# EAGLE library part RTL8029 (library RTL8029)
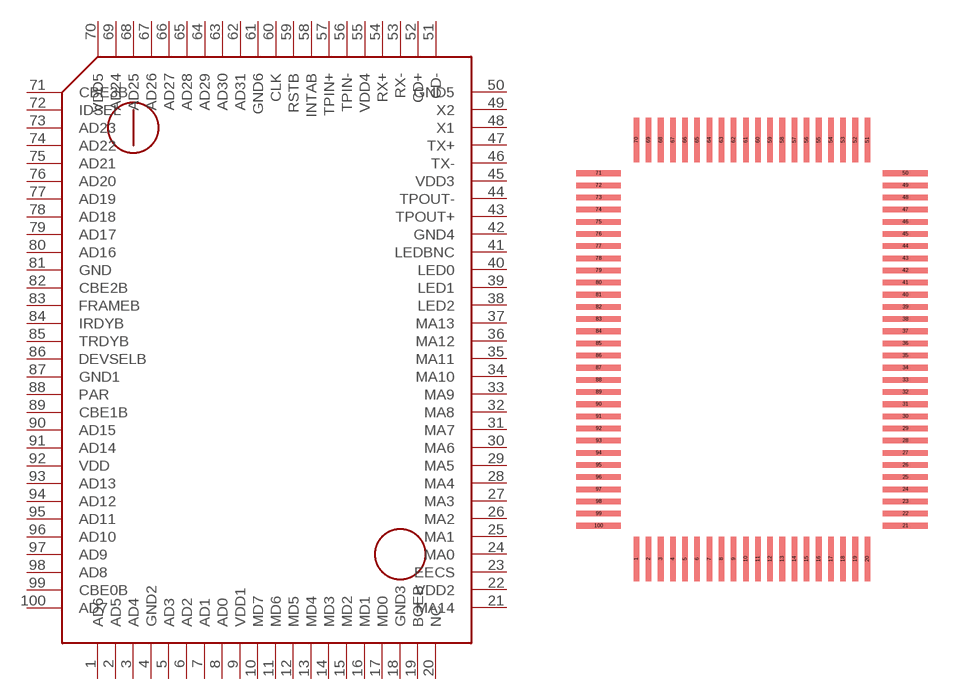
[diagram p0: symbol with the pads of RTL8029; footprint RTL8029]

Designator prefix -

## RTL8029  [RTL8029]
1  AD6
2  AD5
3  AD4
4  GND2
5  AD3
6  AD2
7  AD1
8  AD0
9  VDD1
10  MD7
11  MD6
12  MD5
13  MD4
14  MD3
15  MD2
16  MD1
17  MD0
18  GND3
19  BOEB
20  NC
21  MA14
22  VDD2
23  EECS
24  MA0
25  MA1
26  MA2
27  MA3
28  MA4
29  MA5
30  MA6
31  MA7
32  MA8
33  MA9
34  MA10
35  MA11
36  MA12
37  MA13
38  LED2
39  LED1
40  LED0
41  LEDBNC
42  GND4
43  TPOUT+
44  TPOUT-
45  VDD3
46  TX-
47  TX+
48  X1
49  X2
50  GND5
51  CD-
52  CD+
53  RX-
54  RX+
55  VDD4
56  TPIN-
57  TPIN+
58  INTAB
59  RSTB
60  CLK
61  GND6
62  AD31
63  AD30
64  AD29
65  AD28
66  AD27
67  AD26
68  AD25
69  AD24
70  VDD5
71  CBE3B
72  IDSEL
73  AD23
74  AD22
75  AD21
76  AD20
77  AD19
78  AD18
79  AD17
80  AD16
81  GND
82  CBE2B
83  FRAMEB
84  IRDYB
85  TRDYB
86  DEVSELB
87  GND1
88  PAR
89  CBE1B
90  AD15
91  AD14
92  VDD
93  AD13
94  AD12
95  AD11
96  AD10
97  AD9
98  AD8
99  CBE0B
100  AD7

## Footprint RTL8029 (pad centres in mm)
smd 0.3 x 2.4: 1 -6.175,-11.2; 2 -5.525,-11.2; 3 -4.875,-11.2; 4 -4.225,-11.2; 5 -3.575,-11.2; 6 -2.925,-11.2; 7 -2.275,-11.2; 8 -1.625,-11.2; 9 -0.975,-11.2; 10 -0.325,-11.2; 11 0.325,-11.2; 12 0.975,-11.2; 13 1.625,-11.2; 14 2.275,-11.2; 15 2.925,-11.2; 16 3.575,-11.2; 17 4.225,-11.2; 18 4.875,-11.2; 19 5.525,-11.2; 20 6.175,-11.2; 51 6.175,11.2; 52 5.525,11.2; 53 4.875,11.2; 54 4.225,11.2; 55 3.575,11.2; 56 2.925,11.2; 57 2.275,11.2; 58 1.625,11.2; 59 0.975,11.2; 60 0.325,11.2; 61 -0.325,11.2; 62 -0.975,11.2; 63 -1.625,11.2; 64 -2.275,11.2; 65 -2.925,11.2; 66 -3.575,11.2; 67 -4.225,11.2; 68 -4.875,11.2; 69 -5.525,11.2; 70 -6.175,11.2
smd 2.4 x 0.3: 21 8.2,-9.425; 22 8.2,-8.775; 23 8.2,-8.125; 24 8.2,-7.475; 25 8.2,-6.825; 26 8.2,-6.175; 27 8.2,-5.525; 28 8.2,-4.875; 29 8.2,-4.225; 30 8.2,-3.575; 31 8.2,-2.925; 32 8.2,-2.275; 33 8.2,-1.625; 34 8.2,-0.975; 35 8.2,-0.325; 36 8.2,0.325; 37 8.2,0.975; 38 8.2,1.625; 39 8.2,2.275; 40 8.2,2.925; 41 8.2,3.575; 42 8.2,4.225; 43 8.2,4.875; 44 8.2,5.525; 45 8.2,6.175; 46 8.2,6.825; 47 8.2,7.475; 48 8.2,8.125; 49 8.2,8.775; 50 8.2,9.425; 71 -8.2,9.425; 72 -8.2,8.775; 73 -8.2,8.125; 74 -8.2,7.475; 75 -8.2,6.825; 76 -8.2,6.175; 77 -8.2,5.525; 78 -8.2,4.875; 79 -8.2,4.225; 80 -8.2,3.575; 81 -8.2,2.925; 82 -8.2,2.275; 83 -8.2,1.625; 84 -8.2,0.975; 85 -8.2,0.325; 86 -8.2,-0.325; 87 -8.2,-0.975; 88 -8.2,-1.625; 89 -8.2,-2.275; 90 -8.2,-2.925; 91 -8.2,-3.575; 92 -8.2,-4.225; 93 -8.2,-4.875; 94 -8.2,-5.525; 95 -8.2,-6.175; 96 -8.2,-6.825; 97 -8.2,-7.475; 98 -8.2,-8.125; 99 -8.2,-8.775; 100 -8.2,-9.425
